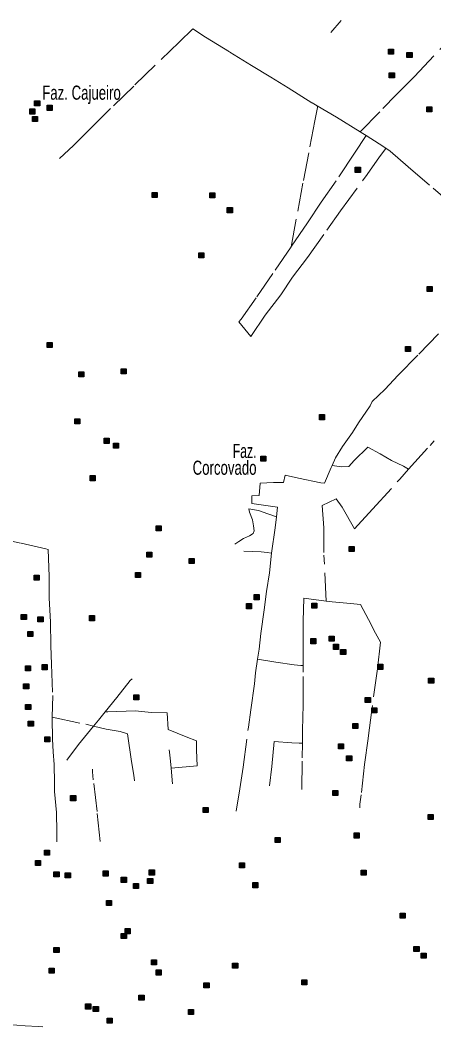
# Model space of a CAD drawing. Extents: x 445.6 to 500, y 8618.1 to 8673.4.
# Drawn here: x 460.52 to 465.21, y 8662 to 8673.41 of the extents above; entities that cross this region are included whole.
import ezdxf
from ezdxf.enums import TextEntityAlignment as Align

# ---------------------------------------------------------------- set-up
doc = ezdxf.new("R2010")
doc.units = 0
doc.header["$LTSCALE"] = 0.064
doc.linetypes.add('DOT_DASHED', pattern=[7.7, 5, -1.2, 0.3, -1.2])
doc.layers.add('2', color=7, linetype='Continuous', lineweight=25)
doc.layers.add('22', color=7, linetype='DOT_DASHED', lineweight=13)
doc.layers.add('61', color=7, linetype='Continuous')

msp = doc.modelspace()

# ---------------------------------------------------------------- hatches: boundary and pattern name
at = {"layer": '2'}
for points in [[(464.6932, 8673.0828), (464.7512, 8673.0828), (464.7512, 8673.0248), (464.6932, 8673.0248)], [(464.9026, 8673.0455), (464.9606, 8673.0455), (464.9606, 8672.9875), (464.9026, 8672.9875)], [(464.7033, 8672.8151), (464.7613, 8672.8151), (464.7613, 8672.7571), (464.7033, 8672.7571)], [(460.6823, 8672.4968), (460.7403, 8672.4968), (460.7403, 8672.4388), (460.6823, 8672.4388)], [(460.6282, 8672.4053), (460.6862, 8672.4053), (460.6862, 8672.3473), (460.6282, 8672.3473)], [(460.8241, 8672.446), (460.8821, 8672.446), (460.8821, 8672.388), (460.8241, 8672.388)], [(465.1289, 8672.4289), (465.1869, 8672.4289), (465.1869, 8672.3709), (465.1289, 8672.3709)], [(460.6586, 8672.3206), (460.7166, 8672.3206), (460.7166, 8672.2626), (460.6586, 8672.2626)], [(464.3175, 8671.744), (464.3755, 8671.744), (464.3755, 8671.686), (464.3175, 8671.686)], [(462.0136, 8671.4593), (462.0716, 8671.4593), (462.0716, 8671.4013), (462.0136, 8671.4013)], [(462.6673, 8671.456), (462.7253, 8671.456), (462.7253, 8671.398), (462.6673, 8671.398)], [(462.8666, 8671.2866), (462.9246, 8671.2866), (462.9246, 8671.2286), (462.8666, 8671.2286)], [(462.5423, 8670.775), (462.6003, 8670.775), (462.6003, 8670.717), (462.5423, 8670.717)], [(465.1325, 8670.3938), (465.1905, 8670.3938), (465.1905, 8670.3358), (465.1325, 8670.3358)], [(460.8246, 8669.7582), (460.8826, 8669.7582), (460.8826, 8669.7002), (460.8246, 8669.7002)], [(464.8861, 8669.7138), (464.9441, 8669.7138), (464.9441, 8669.6558), (464.8861, 8669.6558)], [(461.1843, 8669.4259), (461.2423, 8669.4259), (461.2423, 8669.3679), (461.1843, 8669.3679)], [(461.6639, 8669.4598), (461.7219, 8669.4598), (461.7219, 8669.4018), (461.6639, 8669.4018)], [(463.9114, 8668.9415), (463.9694, 8668.9415), (463.9694, 8668.8835), (463.9114, 8668.8835)], [(461.137, 8668.894), (461.195, 8668.894), (461.195, 8668.836), (461.137, 8668.836)], [(461.4714, 8668.6738), (461.5294, 8668.6738), (461.5294, 8668.6158), (461.4714, 8668.6158)], [(461.5761, 8668.6196), (461.6341, 8668.6196), (461.6341, 8668.5616), (461.5761, 8668.5616)], [(463.246, 8668.4706), (463.304, 8668.4706), (463.304, 8668.4126), (463.246, 8668.4126)], [(461.3126, 8668.2503), (461.3706, 8668.2503), (461.3706, 8668.1923), (461.3126, 8668.1923)], [(462.0609, 8667.6807), (462.1189, 8667.6807), (462.1189, 8667.6227), (462.0609, 8667.6227)], [(461.9551, 8667.3823), (462.0131, 8667.3823), (462.0131, 8667.3243), (461.9551, 8667.3243)], [(464.2464, 8667.4469), (464.3044, 8667.4469), (464.3044, 8667.3889), (464.2464, 8667.3889)], [(462.4346, 8667.3115), (462.4926, 8667.3115), (462.4926, 8667.2535), (462.4346, 8667.2535)], [(460.676, 8667.1217), (460.734, 8667.1217), (460.734, 8667.0637), (460.676, 8667.0637)], [(461.8245, 8667.1522), (461.8825, 8667.1522), (461.8825, 8667.0942), (461.8245, 8667.0942)], [(463.1709, 8666.9015), (463.2289, 8666.9015), (463.2289, 8666.8435), (463.1709, 8666.8435)], [(463.0831, 8666.7999), (463.1411, 8666.7999), (463.1411, 8666.7419), (463.0831, 8666.7419)], [(463.8242, 8666.8066), (463.8822, 8666.8066), (463.8822, 8666.7486), (463.8242, 8666.7486)], [(460.5308, 8666.6779), (460.5888, 8666.6779), (460.5888, 8666.6199), (460.5308, 8666.6199)], [(461.3043, 8666.6643), (461.3623, 8666.6643), (461.3623, 8666.6063), (461.3043, 8666.6063)], [(460.7199, 8666.6508), (460.7779, 8666.6508), (460.7779, 8666.5928), (460.7199, 8666.5928)], [(460.6051, 8666.4848), (460.6631, 8666.4848), (460.6631, 8666.4268), (460.6051, 8666.4268)], [(464.0201, 8666.4305), (464.0781, 8666.4305), (464.0781, 8666.3725), (464.0201, 8666.3725)], [(463.8141, 8666.4034), (463.8721, 8666.4034), (463.8721, 8666.3454), (463.8141, 8666.3454)], [(464.0698, 8666.3389), (464.1278, 8666.3389), (464.1278, 8666.2809), (464.0698, 8666.2809)], [(464.1518, 8666.2814), (464.2098, 8666.2814), (464.2098, 8666.2234), (464.1518, 8666.2234)], [(460.578, 8666.0951), (460.636, 8666.0951), (460.636, 8666.0371), (460.578, 8666.0371)], [(460.7672, 8666.1087), (460.8252, 8666.1087), (460.8252, 8666.0507), (460.7672, 8666.0507)], [(464.5732, 8666.112), (464.6312, 8666.112), (464.6312, 8666.054), (464.5732, 8666.054)], [(460.5573, 8665.8918), (460.6153, 8665.8918), (460.6153, 8665.8338), (460.5573, 8665.8338)], [(465.1489, 8665.9562), (465.2069, 8665.9562), (465.2069, 8665.8982), (465.1489, 8665.8982)], [(461.8057, 8665.7665), (461.8637, 8665.7665), (461.8637, 8665.7085), (461.8057, 8665.7085)], [(460.5809, 8665.658), (460.6389, 8665.658), (460.6389, 8665.6), (460.5809, 8665.6)], [(464.4304, 8665.7359), (464.4884, 8665.7359), (464.4884, 8665.6779), (464.4304, 8665.6779)], [(464.5047, 8665.6207), (464.5627, 8665.6207), (464.5627, 8665.5627), (464.5047, 8665.5627)], [(460.6113, 8665.4683), (460.6693, 8665.4683), (460.6693, 8665.4103), (460.6113, 8665.4103)], [(464.2895, 8665.4411), (464.3475, 8665.4411), (464.3475, 8665.3831), (464.2895, 8665.3831)], [(460.7971, 8665.2921), (460.8551, 8665.2921), (460.8551, 8665.2341), (460.7971, 8665.2341)], [(464.1274, 8665.2107), (464.1854, 8665.2107), (464.1854, 8665.1527), (464.1274, 8665.1527)], [(464.2186, 8665.0752), (464.2766, 8665.0752), (464.2766, 8665.0172), (464.2186, 8665.0172)], [(461.091, 8664.6247), (461.149, 8664.6247), (461.149, 8664.5667), (461.091, 8664.5667)], [(464.0632, 8664.6822), (464.1212, 8664.6822), (464.1212, 8664.6242), (464.0632, 8664.6242)], [(462.5918, 8664.4898), (462.6498, 8664.4898), (462.6498, 8664.4318), (462.5918, 8664.4318)], [(465.1431, 8664.4112), (465.2011, 8664.4112), (465.2011, 8664.3532), (465.1431, 8664.3532)], [(463.4079, 8664.1503), (463.4659, 8664.1503), (463.4659, 8664.0923), (463.4079, 8664.0923)], [(464.3054, 8664.2011), (464.3634, 8664.2011), (464.3634, 8664.1431), (464.3054, 8664.1431)], [(460.794, 8664.0078), (460.852, 8664.0078), (460.852, 8663.9498), (460.794, 8663.9498)], [(460.6927, 8663.8893), (460.7507, 8663.8893), (460.7507, 8663.8313), (460.6927, 8663.8313)], [(463.0045, 8663.8625), (463.0625, 8663.8625), (463.0625, 8663.8045), (463.0045, 8663.8045)], [(460.9021, 8663.7605), (460.9601, 8663.7605), (460.9601, 8663.7025), (460.9021, 8663.7025)], [(461.0305, 8663.7504), (461.0885, 8663.7504), (461.0885, 8663.6924), (461.0305, 8663.6924)], [(461.4595, 8663.7707), (461.5175, 8663.7707), (461.5175, 8663.7127), (461.4595, 8663.7127)], [(461.6655, 8663.6995), (461.7235, 8663.6995), (461.7235, 8663.6415), (461.6655, 8663.6415)], [(461.982, 8663.7816), (462.04, 8663.7816), (462.04, 8663.7236), (461.982, 8663.7236)], [(464.3842, 8663.781), (464.4422, 8663.781), (464.4422, 8663.723), (464.3842, 8663.723)], [(461.804, 8663.6284), (461.862, 8663.6284), (461.862, 8663.5704), (461.804, 8663.5704)], [(461.9628, 8663.686), (462.0208, 8663.686), (462.0208, 8663.628), (461.9628, 8663.628)], [(463.1565, 8663.6389), (463.2145, 8663.6389), (463.2145, 8663.5809), (463.1565, 8663.5809)], [(461.4966, 8663.4353), (461.5546, 8663.4353), (461.5546, 8663.3773), (461.4966, 8663.3773)], [(464.8264, 8663.2921), (464.8844, 8663.2921), (464.8844, 8663.2341), (464.8264, 8663.2341)], [(461.6655, 8663.0626), (461.7235, 8663.0626), (461.7235, 8663.0046), (461.6655, 8663.0046)], [(461.7094, 8663.1168), (461.7674, 8663.1168), (461.7674, 8663.0588), (461.7094, 8663.0588)], [(460.9021, 8662.9038), (460.9601, 8662.9038), (460.9601, 8662.8458), (460.9021, 8662.8458)], [(464.982, 8662.914), (465.04, 8662.914), (465.04, 8662.856), (464.982, 8662.856)], [(465.0649, 8662.8392), (465.1229, 8662.8392), (465.1229, 8662.7812), (465.0649, 8662.7812)], [(460.8481, 8662.67), (460.9061, 8662.67), (460.9061, 8662.612), (460.8481, 8662.612)], [(462.0067, 8662.7644), (462.0647, 8662.7644), (462.0647, 8662.7064), (462.0067, 8662.7064)], [(462.9268, 8662.7275), (462.9848, 8662.7275), (462.9848, 8662.6695), (462.9268, 8662.6695)], [(462.0607, 8662.6493), (462.1187, 8662.6493), (462.1187, 8662.5913), (462.0607, 8662.5913)], [(462.6026, 8662.5039), (462.6606, 8662.5039), (462.6606, 8662.4459), (462.6026, 8662.4459)], [(463.7111, 8662.5363), (463.7691, 8662.5363), (463.7691, 8662.4783), (463.7111, 8662.4783)], [(461.8648, 8662.3647), (461.9228, 8662.3647), (461.9228, 8662.3067), (461.8648, 8662.3067)], [(461.2602, 8662.2634), (461.3182, 8662.2634), (461.3182, 8662.2054), (461.2602, 8662.2054)], [(461.348, 8662.2363), (461.406, 8662.2363), (461.406, 8662.1783), (461.348, 8662.1783)], [(461.5034, 8662.1042), (461.5614, 8662.1042), (461.5614, 8662.0462), (461.5034, 8662.0462)], [(462.4255, 8662.202), (462.4835, 8662.202), (462.4835, 8662.144), (462.4255, 8662.144)]]:
    msp.add_hatch(color=256, dxfattribs=at).paths.add_polyline_path(points)

# ---------------------------------------------------------------- linework, layer by layer
for points in [[(464.6932, 8673.0828), (464.7512, 8673.0828), (464.7512, 8673.0248), (464.6932, 8673.0248)], [(464.9026, 8673.0455), (464.9606, 8673.0455), (464.9606, 8672.9875), (464.9026, 8672.9875)], [(464.7033, 8672.8151), (464.7613, 8672.8151), (464.7613, 8672.7571), (464.7033, 8672.7571)], [(460.6823, 8672.4968), (460.7403, 8672.4968), (460.7403, 8672.4388), (460.6823, 8672.4388)], [(460.6282, 8672.4053), (460.6862, 8672.4053), (460.6862, 8672.3473), (460.6282, 8672.3473)], [(460.8241, 8672.446), (460.8821, 8672.446), (460.8821, 8672.388), (460.8241, 8672.388)], [(465.1289, 8672.4289), (465.1869, 8672.4289), (465.1869, 8672.3709), (465.1289, 8672.3709)], [(460.6586, 8672.3206), (460.7166, 8672.3206), (460.7166, 8672.2626), (460.6586, 8672.2626)], [(464.3175, 8671.744), (464.3755, 8671.744), (464.3755, 8671.686), (464.3175, 8671.686)], [(462.0136, 8671.4593), (462.0716, 8671.4593), (462.0716, 8671.4013), (462.0136, 8671.4013)], [(462.6673, 8671.456), (462.7253, 8671.456), (462.7253, 8671.398), (462.6673, 8671.398)], [(462.8666, 8671.2866), (462.9246, 8671.2866), (462.9246, 8671.2286), (462.8666, 8671.2286)], [(462.5423, 8670.775), (462.6003, 8670.775), (462.6003, 8670.717), (462.5423, 8670.717)], [(465.1325, 8670.3938), (465.1905, 8670.3938), (465.1905, 8670.3358), (465.1325, 8670.3358)], [(460.8246, 8669.7582), (460.8826, 8669.7582), (460.8826, 8669.7002), (460.8246, 8669.7002)], [(464.8861, 8669.7138), (464.9441, 8669.7138), (464.9441, 8669.6558), (464.8861, 8669.6558)], [(461.1843, 8669.4259), (461.2423, 8669.4259), (461.2423, 8669.3679), (461.1843, 8669.3679)], [(461.6639, 8669.4598), (461.7219, 8669.4598), (461.7219, 8669.4018), (461.6639, 8669.4018)], [(463.9114, 8668.9415), (463.9694, 8668.9415), (463.9694, 8668.8835), (463.9114, 8668.8835)], [(461.137, 8668.894), (461.195, 8668.894), (461.195, 8668.836), (461.137, 8668.836)], [(461.4714, 8668.6738), (461.5294, 8668.6738), (461.5294, 8668.6158), (461.4714, 8668.6158)], [(461.5761, 8668.6196), (461.6341, 8668.6196), (461.6341, 8668.5616), (461.5761, 8668.5616)], [(463.246, 8668.4706), (463.304, 8668.4706), (463.304, 8668.4126), (463.246, 8668.4126)], [(461.3126, 8668.2503), (461.3706, 8668.2503), (461.3706, 8668.1923), (461.3126, 8668.1923)], [(462.0609, 8667.6807), (462.1189, 8667.6807), (462.1189, 8667.6227), (462.0609, 8667.6227)], [(461.9551, 8667.3823), (462.0131, 8667.3823), (462.0131, 8667.3243), (461.9551, 8667.3243)], [(464.2464, 8667.4469), (464.3044, 8667.4469), (464.3044, 8667.3889), (464.2464, 8667.3889)], [(462.4346, 8667.3115), (462.4926, 8667.3115), (462.4926, 8667.2535), (462.4346, 8667.2535)], [(460.676, 8667.1217), (460.734, 8667.1217), (460.734, 8667.0637), (460.676, 8667.0637)], [(461.8245, 8667.1522), (461.8825, 8667.1522), (461.8825, 8667.0942), (461.8245, 8667.0942)], [(463.1709, 8666.9015), (463.2289, 8666.9015), (463.2289, 8666.8435), (463.1709, 8666.8435)], [(463.0831, 8666.7999), (463.1411, 8666.7999), (463.1411, 8666.7419), (463.0831, 8666.7419)], [(463.8242, 8666.8066), (463.8822, 8666.8066), (463.8822, 8666.7486), (463.8242, 8666.7486)], [(460.5308, 8666.6779), (460.5888, 8666.6779), (460.5888, 8666.6199), (460.5308, 8666.6199)], [(461.3043, 8666.6643), (461.3623, 8666.6643), (461.3623, 8666.6063), (461.3043, 8666.6063)], [(460.7199, 8666.6508), (460.7779, 8666.6508), (460.7779, 8666.5928), (460.7199, 8666.5928)], [(460.6051, 8666.4848), (460.6631, 8666.4848), (460.6631, 8666.4268), (460.6051, 8666.4268)], [(464.0201, 8666.4305), (464.0781, 8666.4305), (464.0781, 8666.3725), (464.0201, 8666.3725)], [(463.8141, 8666.4034), (463.8721, 8666.4034), (463.8721, 8666.3454), (463.8141, 8666.3454)], [(464.0698, 8666.3389), (464.1278, 8666.3389), (464.1278, 8666.2809), (464.0698, 8666.2809)], [(464.1518, 8666.2814), (464.2098, 8666.2814), (464.2098, 8666.2234), (464.1518, 8666.2234)], [(460.578, 8666.0951), (460.636, 8666.0951), (460.636, 8666.0371), (460.578, 8666.0371)], [(460.7672, 8666.1087), (460.8252, 8666.1087), (460.8252, 8666.0507), (460.7672, 8666.0507)], [(464.5732, 8666.112), (464.6312, 8666.112), (464.6312, 8666.054), (464.5732, 8666.054)], [(460.5573, 8665.8918), (460.6153, 8665.8918), (460.6153, 8665.8338), (460.5573, 8665.8338)], [(465.1489, 8665.9562), (465.2069, 8665.9562), (465.2069, 8665.8982), (465.1489, 8665.8982)], [(461.8057, 8665.7665), (461.8637, 8665.7665), (461.8637, 8665.7085), (461.8057, 8665.7085)], [(460.5809, 8665.658), (460.6389, 8665.658), (460.6389, 8665.6), (460.5809, 8665.6)], [(464.4304, 8665.7359), (464.4884, 8665.7359), (464.4884, 8665.6779), (464.4304, 8665.6779)], [(464.5047, 8665.6207), (464.5627, 8665.6207), (464.5627, 8665.5627), (464.5047, 8665.5627)], [(460.6113, 8665.4683), (460.6693, 8665.4683), (460.6693, 8665.4103), (460.6113, 8665.4103)], [(464.2895, 8665.4411), (464.3475, 8665.4411), (464.3475, 8665.3831), (464.2895, 8665.3831)], [(460.7971, 8665.2921), (460.8551, 8665.2921), (460.8551, 8665.2341), (460.7971, 8665.2341)], [(464.1274, 8665.2107), (464.1854, 8665.2107), (464.1854, 8665.1527), (464.1274, 8665.1527)], [(464.2186, 8665.0752), (464.2766, 8665.0752), (464.2766, 8665.0172), (464.2186, 8665.0172)], [(461.091, 8664.6247), (461.149, 8664.6247), (461.149, 8664.5667), (461.091, 8664.5667)], [(464.0632, 8664.6822), (464.1212, 8664.6822), (464.1212, 8664.6242), (464.0632, 8664.6242)], [(462.5918, 8664.4898), (462.6498, 8664.4898), (462.6498, 8664.4318), (462.5918, 8664.4318)], [(465.1431, 8664.4112), (465.2011, 8664.4112), (465.2011, 8664.3532), (465.1431, 8664.3532)], [(463.4079, 8664.1503), (463.4659, 8664.1503), (463.4659, 8664.0923), (463.4079, 8664.0923)], [(464.3054, 8664.2011), (464.3634, 8664.2011), (464.3634, 8664.1431), (464.3054, 8664.1431)], [(460.794, 8664.0078), (460.852, 8664.0078), (460.852, 8663.9498), (460.794, 8663.9498)], [(460.6927, 8663.8893), (460.7507, 8663.8893), (460.7507, 8663.8313), (460.6927, 8663.8313)], [(463.0045, 8663.8625), (463.0625, 8663.8625), (463.0625, 8663.8045), (463.0045, 8663.8045)], [(460.9021, 8663.7605), (460.9601, 8663.7605), (460.9601, 8663.7025), (460.9021, 8663.7025)], [(461.0305, 8663.7504), (461.0885, 8663.7504), (461.0885, 8663.6924), (461.0305, 8663.6924)], [(461.4595, 8663.7707), (461.5175, 8663.7707), (461.5175, 8663.7127), (461.4595, 8663.7127)], [(461.6655, 8663.6995), (461.7235, 8663.6995), (461.7235, 8663.6415), (461.6655, 8663.6415)], [(461.982, 8663.7816), (462.04, 8663.7816), (462.04, 8663.7236), (461.982, 8663.7236)], [(464.3842, 8663.781), (464.4422, 8663.781), (464.4422, 8663.723), (464.3842, 8663.723)], [(461.804, 8663.6284), (461.862, 8663.6284), (461.862, 8663.5704), (461.804, 8663.5704)], [(461.9628, 8663.686), (462.0208, 8663.686), (462.0208, 8663.628), (461.9628, 8663.628)], [(463.1565, 8663.6389), (463.2145, 8663.6389), (463.2145, 8663.5809), (463.1565, 8663.5809)], [(461.4966, 8663.4353), (461.5546, 8663.4353), (461.5546, 8663.3773), (461.4966, 8663.3773)], [(464.8264, 8663.2921), (464.8844, 8663.2921), (464.8844, 8663.2341), (464.8264, 8663.2341)], [(461.6655, 8663.0626), (461.7235, 8663.0626), (461.7235, 8663.0046), (461.6655, 8663.0046)], [(461.7094, 8663.1168), (461.7674, 8663.1168), (461.7674, 8663.0588), (461.7094, 8663.0588)], [(460.9021, 8662.9038), (460.9601, 8662.9038), (460.9601, 8662.8458), (460.9021, 8662.8458)], [(464.982, 8662.914), (465.04, 8662.914), (465.04, 8662.856), (464.982, 8662.856)], [(465.0649, 8662.8392), (465.1229, 8662.8392), (465.1229, 8662.7812), (465.0649, 8662.7812)], [(460.8481, 8662.67), (460.9061, 8662.67), (460.9061, 8662.612), (460.8481, 8662.612)], [(462.0067, 8662.7644), (462.0647, 8662.7644), (462.0647, 8662.7064), (462.0067, 8662.7064)], [(462.9268, 8662.7275), (462.9848, 8662.7275), (462.9848, 8662.6695), (462.9268, 8662.6695)], [(462.0607, 8662.6493), (462.1187, 8662.6493), (462.1187, 8662.5913), (462.0607, 8662.5913)], [(462.6026, 8662.5039), (462.6606, 8662.5039), (462.6606, 8662.4459), (462.6026, 8662.4459)], [(463.7111, 8662.5363), (463.7691, 8662.5363), (463.7691, 8662.4783), (463.7111, 8662.4783)], [(461.8648, 8662.3647), (461.9228, 8662.3647), (461.9228, 8662.3067), (461.8648, 8662.3067)], [(461.2602, 8662.2634), (461.3182, 8662.2634), (461.3182, 8662.2054), (461.2602, 8662.2054)], [(461.348, 8662.2363), (461.406, 8662.2363), (461.406, 8662.1783), (461.348, 8662.1783)], [(461.5034, 8662.1042), (461.5614, 8662.1042), (461.5614, 8662.0462), (461.5034, 8662.0462)], [(462.4255, 8662.202), (462.4835, 8662.202), (462.4835, 8662.144), (462.4255, 8662.144)]]:
    msp.add_lwpolyline(points, close=True, dxfattribs=at)
at = {"layer": '22'}
for p, q in [((464.1591, 8673.4075), (464.0402, 8673.2701)), ((462.2473, 8664.7594), (462.2309, 8664.9337))]:
    msp.add_line(p, q, dxfattribs=at)
for points in [[(464.3711, 8672.1461), (464.6308, 8672.409), (464.7799, 8672.563), (464.9881, 8672.7735), (465.5838, 8673.4113)], [(460.9664, 8671.8451), (461.1229, 8671.9924), (461.3156, 8672.1849), (461.5778, 8672.4415), (461.8204, 8672.6764), (462.1186, 8672.9665), (462.3201, 8673.1606), (462.4743, 8673.312), (462.6208, 8673.2196), (462.8958, 8673.0502), (463.1426, 8672.8962), (463.3621, 8672.7669), (463.5549, 8672.6437), (463.8273, 8672.4743), (463.8873, 8672.4392)], [(463.5922, 8670.8426), (463.665, 8671.2483), (463.7306, 8671.5939), (463.8017, 8671.9742), (463.8573, 8672.2694), (463.8877, 8672.4222), (463.8873, 8672.4392)], [(463.8873, 8672.4392), (464.1059, 8672.3113), (464.3711, 8672.1461)], [(464.3711, 8672.1461), (464.3861, 8672.1368), (464.4413, 8672.1024)], [(464.4413, 8672.1024), (464.3082, 8671.9028), (464.1016, 8671.5922), (463.9317, 8671.3468), (463.7769, 8671.1128), (463.5922, 8670.8426)], [(464.4413, 8672.1024), (464.5901, 8672.0099), (464.6641, 8671.9591)], [(463.5922, 8670.8426), (463.3839, 8670.5392), (463.1931, 8670.2651), (463.0254, 8670.0233), (462.9966, 8669.9919), (463.1352, 8669.8249), (463.2946, 8670.0676), (463.4724, 8670.2974), (463.6066, 8670.4971), (463.7765, 8670.7216), (463.994, 8671.0311), (464.1509, 8671.2504), (464.4521, 8671.6618), (464.5935, 8671.864), (464.651, 8671.9423), (464.6641, 8671.9591)], [(464.6641, 8671.9591), (464.7135, 8671.9252), (464.9165, 8671.7481), (465.1999, 8671.5055), (465.4621, 8671.2822), (465.6009, 8671.159), (465.642, 8671.1256), (466.1156, 8670.7528)], [(464.0555, 8668.3656), (464.0932, 8668.453), (464.1736, 8668.5805), (464.2847, 8668.7387), (464.3557, 8668.8473), (464.4861, 8669.0399), (464.5098, 8669.0895), (464.654, 8669.2265), (464.803, 8669.387), (465.0378, 8669.6271), (465.3216, 8669.9152), (465.573, 8670.155), (465.7882, 8670.3793), (465.9757, 8670.5956), (466.1156, 8670.7528)], [(464.9215, 8668.3221), (465.1649, 8668.5928), (465.2099, 8668.646)], [(464.0555, 8668.3656), (464.1605, 8668.3506), (464.2443, 8668.3534), (464.303, 8668.4203), (464.4595, 8668.5738), (464.5992, 8668.4957), (464.7278, 8668.4231), (464.8647, 8668.3562), (464.9215, 8668.3221)], [(463.425, 8667.7837), (463.4372, 8667.8933), (463.1439, 8667.9358), (463.1438, 8668.022), (463.2289, 8668.0267), (463.2408, 8668.166), (463.3898, 8668.1708), (463.5033, 8668.1708), (463.5245, 8668.2534), (463.6735, 8668.2204), (463.9266, 8668.1684), (463.9668, 8668.1637), (464.0448, 8668.3408), (464.0555, 8668.3656)], [(463.9868, 8666.8286), (463.9612, 8667.379), (463.9612, 8667.6567), (463.9438, 8667.9116), (464.1003, 8667.9854), (464.1698, 8667.8942), (464.3089, 8667.6469), (464.5131, 8667.8682), (464.8216, 8668.211), (464.9215, 8668.3221)], [(463.425, 8667.7837), (463.325, 8667.8188), (463.2212, 8667.8543), (463.1114, 8667.8751), (463.1203, 8667.8366), (463.1529, 8667.7506), (463.1648, 8667.6795), (463.1707, 8667.6232), (463.1618, 8667.5936), (463.1203, 8667.567), (463.0521, 8667.5373), (462.9957, 8667.5047), (462.9518, 8667.4745)], [(463.3684, 8667.3715), (463.3685, 8667.3723), (463.4111, 8667.6595), (463.425, 8667.7837)], [(459.8363, 8667.6409), (460.2101, 8667.5563), (460.5302, 8667.4836), (460.809, 8667.4207), (460.8372, 8667.4129), (460.8493, 8667.1078), (460.8469, 8666.8609), (460.8609, 8666.5929), (460.8658, 8666.3217), (460.8732, 8666.1144), (460.8877, 8665.7585), (460.8831, 8665.5131)], [(463.0532, 8667.3936), (463.2508, 8667.3862), (463.3191, 8667.3803), (463.3684, 8667.3715)], [(463.2094, 8666.1701), (463.2265, 8666.2855), (463.2478, 8666.4626), (463.2857, 8666.7308), (463.3093, 8666.9363), (463.3449, 8667.148), (463.3684, 8667.3715)], [(463.728, 8666.0987), (463.7281, 8666.3406), (463.7281, 8666.6004), (463.7338, 8666.8621), (463.9868, 8666.8286)], [(463.9868, 8666.8286), (464.0569, 8666.8193), (464.2628, 8666.7993), (464.3771, 8666.7907), (464.4658, 8666.6194), (464.547, 8666.4641), (464.6042, 8666.3613), (464.5699, 8666.0616), (464.504, 8665.5944), (464.4639, 8665.2704), (464.4239, 8664.9764), (464.3837, 8664.6322), (464.3694, 8664.5265), (464.3695, 8664.4848)], [(462.9681, 8664.448), (463.0089, 8664.7018), (463.0468, 8664.9474), (463.1059, 8665.3986), (463.1343, 8665.5969), (463.1745, 8665.8921), (463.1863, 8666.014), (463.2094, 8666.1701)], [(463.2094, 8666.1701), (463.4178, 8666.1348), (463.6258, 8666.1077), (463.7012, 8666.0987), (463.728, 8666.0987)], [(463.718, 8665.2184), (463.7194, 8665.3662), (463.7252, 8665.6536), (463.728, 8666.0219), (463.728, 8666.0987)], [(461.4836, 8665.5747), (461.6136, 8665.7365), (461.7647, 8665.9303), (461.7871, 8665.9493)], [(461.3515, 8665.4121), (461.4058, 8665.4779), (461.4836, 8665.5747)], [(462.2309, 8664.9337), (462.5245, 8664.9633), (462.5184, 8665.1407), (462.5184, 8665.246), (462.401, 8665.2911), (462.1962, 8665.3722), (462.1842, 8665.5617), (462.0065, 8665.5677), (461.8222, 8665.5837), (461.5121, 8665.5747), (461.4836, 8665.5747)], [(460.8831, 8665.5131), (460.8829, 8665.5029), (460.8854, 8665.2632), (460.8926, 8665.1214), (460.9047, 8664.9786), (460.9096, 8664.7704), (460.9096, 8664.6711), (460.9294, 8664.4319), (460.9343, 8664.2116), (460.9343, 8664.099)], [(460.8831, 8665.5131), (461.2622, 8665.433), (461.3515, 8665.4121)], [(461.0482, 8665.0262), (461.18, 8665.2043), (461.3515, 8665.4121)], [(461.3515, 8665.4121), (461.4942, 8665.3787), (461.6517, 8665.3501), (461.7348, 8665.3243), (461.7806, 8665.0126), (461.8064, 8664.8553), (461.8147, 8664.7932)], [(463.3444, 8664.7337), (463.3722, 8664.956), (463.3964, 8665.2372), (463.5975, 8665.2211), (463.6806, 8665.2184), (463.718, 8665.2184)], [(463.7117, 8664.6953), (463.7165, 8665.0522), (463.718, 8665.2184)], [(462.2309, 8664.9337), (462.2233, 8665.0144), (462.2113, 8665.1167), (462.2092, 8665.1435)], [(461.4241, 8664.1038), (461.3906, 8664.4443), (461.3469, 8664.8038), (461.3402, 8664.8929), (461.3404, 8664.9237)], [(458.3082, 8662.7989), (458.4189, 8662.8943), (458.4561, 8662.9359), (458.6007, 8662.844), (458.7869, 8662.7128), (459.041, 8662.5465), (459.2645, 8662.4087), (459.4586, 8662.2828), (459.6032, 8662.1953), (459.7303, 8662.1056), (459.9997, 8662.075), (460.2528, 8662.0459), (460.3864, 8662.0306), (460.577, 8662.0152), (460.7238, 8662.0087), (460.7766, 8662.0039)]]:
    msp.add_lwpolyline(points, dxfattribs=at)

# ---------------------------------------------------------------- texts
at = {"layer": '61', "width": 0.7}
msp.add_text('Faz. Cajueiro', height=0.16, dxfattribs=at).set_placement((460.7688, 8672.5095))
at = {"layer": '61'}
for s, width, p in [('Faz.', 0.65, (463.1983, 8668.4498)), ('Corcovado', 0.7, (463.1983, 8668.2598))]:
    msp.add_text(s, height=0.16, dxfattribs=dict(at, width=width)).set_placement(p, align=Align.RIGHT)

doc.saveas('drawing.dxf')
